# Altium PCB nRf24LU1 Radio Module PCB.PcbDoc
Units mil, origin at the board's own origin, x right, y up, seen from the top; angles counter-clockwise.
Board outline 2945 x 691.05 mil, 2 copper layers (Top Layer, Bottom Layer); 44 components, 44 nets, 168 pads, 119 vias.
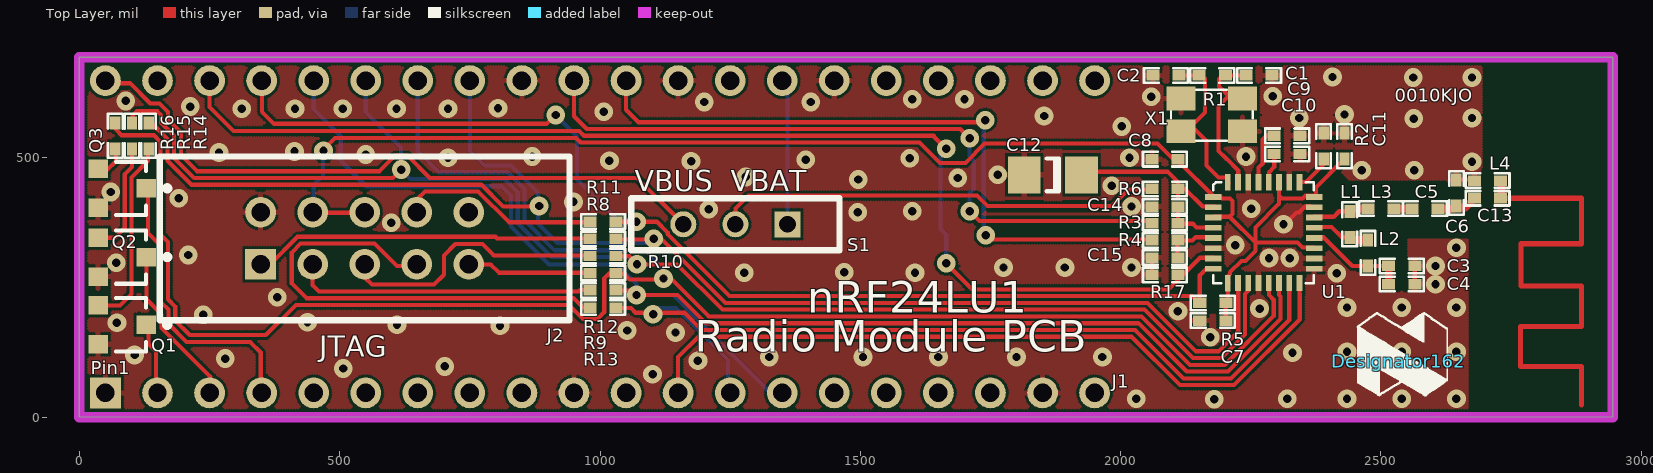
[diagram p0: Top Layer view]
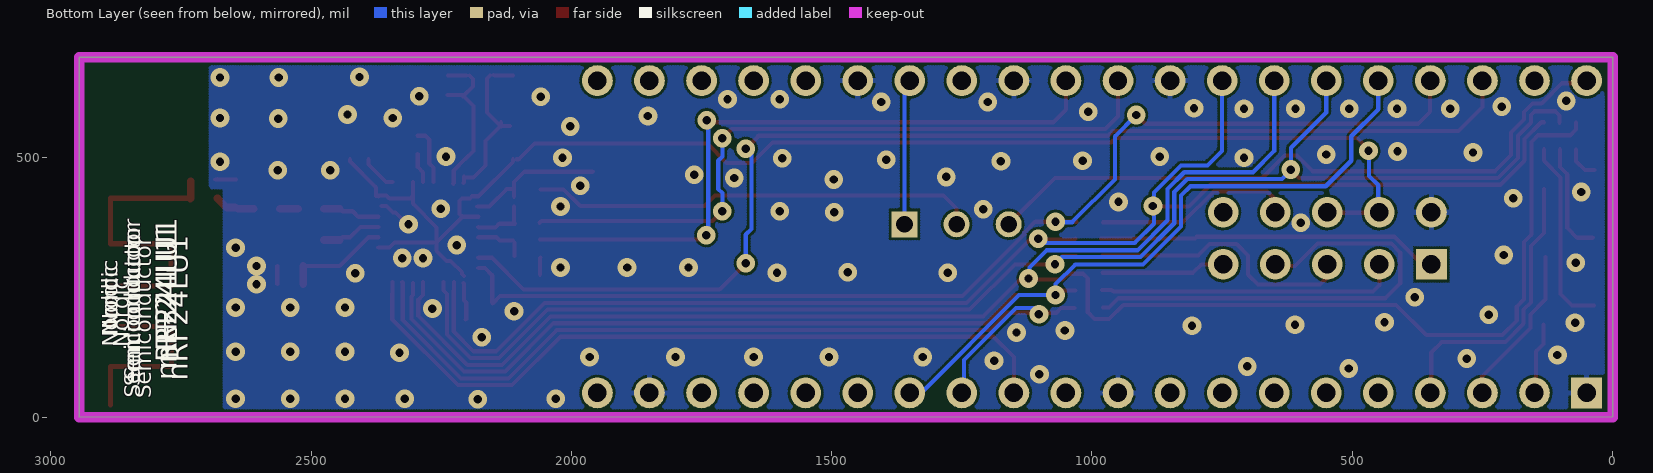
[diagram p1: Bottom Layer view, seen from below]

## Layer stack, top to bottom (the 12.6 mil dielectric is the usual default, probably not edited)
Top Layer: signal copper 1.4
Dielectric: dielectric 12.6, FR-4, Dk 4.8
Bottom Layer: signal copper 1.4

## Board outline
0,1 0,691.53 2945,691.53 2945,0.47

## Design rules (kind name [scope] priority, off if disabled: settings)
Clearance [All] p1: gap=5
ComponentClearance [All] p1 off: gap=10 collisioncheckmode=3 verticalgap=10
PolygonConnect PolygonConnect_1 [IsVia and InNet(GND)] p1: connectstyle=Direct reliefconductorwidth=10 reliefentries=4 polygonreliefangle="90 Angle"
PolygonConnect [All] p2: connectstyle=Relief reliefconductorwidth=10 reliefentries=4 polygonreliefangle="90 Angle"
RoomDefinition "nRF24LU1 Radio Module PCB" [InComponentClass('nRF24LU1 Radio Module PCB')] p1 off: confinementstyle=ConfineIn formatcopy=TRUE lockcomponents=FALSE outline 3275,55 3406,55 3406,259 3275,259
RoutingVias [All] p1: holewidth=10 width=20 viastyle="Through Hole" minholewidth=6 minwidth=10 maxholewidth=28 maxwidth=50
SolderMaskExpansion [All] p1: expansion=4
TestPointUsage [All] p1: valid=0 allowmultiple=FALSE
Testpoint [All] p1: side=15 testpointundercomponent=TRUE minsize=40 maxsize=100 preferedsize=60 minholesize=0 maxholesize=40 preferedholesize=32 testpointgrid=1 style=1023 order=0-112345678
Width [All] p1: maxlimit=50 minlimit=6 preferedwidth=10 toplayer_prefwidth=8 bottomlayer_prefwidth=8 minimp=50.000000 maximp=50.000000 favimp=50.000000
18 further rules are at their usual default settings.

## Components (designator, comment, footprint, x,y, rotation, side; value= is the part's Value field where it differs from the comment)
C1 "NPO, +/-2% 50V" 0402s 2266,657 r0 top
C2 "NPO, +/-2% 50V" 0402s 2087,657 r0 top
C3 "X7R, +/-10% 50V" 0402s 2540,291 r180 top
C4 "NP0 +/-0.25pF, 50V" 0402s 2540,256 r180 top
C5 "NP0 +/-0.1pF, 50V" 0402s 2585,401 r180 top
C6 "NP0 +/-0.1pF, 50V" 0402s 2645,431 r90 top
C7 "X7R, +/-10% 50V" 0402s 2177,186 r180 top
C8 "X7R, +/-10% 50V" 0402s 2085,496 r180 top
C9 "X7R, +/-10% 50V" 0402s 2320,541 r0 top
C10 "X7R, +/-10% 50V" 0402s 2320,506 r0 top
C11 "X7R, +/-10% 50V" 0402s 2430,521 r90 top
C12 "Tantal  10V" C1206 1870,466 r180 top
C13 "NP0 +/-0.25pF, 50V" 0402s 2705,421 r180 top
C14 "NP0, +/-10% 50V" 0402s 2085,405 r180 top
C15 "" 0402s 2085,307 r180 top
Designator162 "Comment" NordicSemi1 2534,108 r180 top
J1 "Elfa 48-155-10" DIP40 50,47 r90 top
J2 "Header 2x5 pin" IDC2X5 548,344 r0 top
L1 "Chip inductor +/-5%  Murata LQP15" 0402s 2440,371 r270 top
L2 "Chip Inductor +/-5%  Murata LQP15" 0402s 2475,316 r90 top
L3 "Chip inductor +/-5%  Murata LQP15" 0402s 2500,401 r0 top
L4 "Chip inductor +/-5% Murata LQP15" 0402s 2705,455 r0 top
Q1 "BC847C" SOT23 82,178 r270 top
Q2 "BC847C" SOT23 82,308 r270 top
Q3 "BC847C" SOT23 82,440 r270 top
R1 "5%" 0402s 2176,657 r180 top
R2 "1%" 0402s 2390,521 r270 top
R3 "5%" 0402s 2085,373 r180 top
R4 "5%" 0402s 2085,340 r180 top
R5 "5%" 0402s 2177,220 r0 top
R6 "5%" 0402s 2085,439 r180 top
R8 "" 0402s 1006,343 r180 top
R9 "" 0402s 1006,244 r180 top
R10 "" 0402s 1006,310 r180 top
R11 "" 0402s 1006,376 r180 top
R12 "" 0402s 1006,277 r180 top
R13 "" 0402s 1006,211 r180 top
R14 "5%" 0402s 133,541 r270 top
R15 "5%" 0402s 101,541 r270 top
R16 "5%" 0402s 69,541 r270 top
R17 "5%" 0402s 2085,274 r0 top
S1 "ELFA 35-365-21" "SW mini2" 1360,371 r180 top
U1 "nRF24LU1" QFN32L/5x5 2178,258 r0 top
X1 "TSX4025 16MHz, CL=9pF" BT-XTAL 2175,581 r180 top

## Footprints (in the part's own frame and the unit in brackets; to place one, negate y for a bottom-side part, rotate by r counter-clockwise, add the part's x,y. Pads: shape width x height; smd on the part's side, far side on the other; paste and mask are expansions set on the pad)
0402s [mil]
  rect 25x20 smd: 1(-25,0) 2(25,0)
  silkscreen extent -42,-14 42,14
BT-XTAL [mm]
  rect 1.4x1.15 smd: 1(-1.498,-0.801) 2(1.498,-0.801) 3(1.498,0.801) 4(-1.498,0.801)
  silkscreen extent -2,-1.23 1.98,1.26
C1206 [mm] "Chip Capacitor; Body 3.2 x 1.6 mm (LxW typ)"
  rect 1.6x1.8 smd: 1(-1.4,0) 2(1.4,0)
  silkscreen extent -0.3,-0.8 0.3,0.8
DIP40 [mm]
  rect 1.5x1.5 hole 0.9: 1(0,0)
  round 1.5 hole 0.9: 2(0,-2.54) 3(0,-5.08) 4(0,-7.62) 5(0,-10.16) 6(0,-12.7) 7(0,-15.24) 8(0,-17.78) 9(0,-20.32) 10(0,-22.86) 11(0,-25.4) 12(0,-27.94) 13(0,-30.48) 14(0,-33.02) 15(0,-35.56) 16(0,-38.1) 17(0,-40.64) 18(0,-43.18) 19(0,-45.72) 20(0,-48.26) 21(15.24,-48.26) 22(15.24,-45.72) 23(15.24,-43.18) 24(15.24,-40.64) 25(15.24,-38.1) 26(15.24,-35.56) 27(15.24,-33.02) 28(15.24,-30.48) 29(15.24,-27.94) 30(15.24,-25.4) 31(15.24,-22.86) 32(15.24,-20.32) 33(15.24,-17.78) 34(15.24,-15.24) 35(15.24,-12.7) 36(15.24,-10.16) 37(15.24,-7.62) 38(15.24,-5.08) 39(15.24,-2.54) 40(15.24,0)
IDC2X5 [mm]
  rect 1.5x1.5 hole 0.9: 1(-5.08,-1.27)
  round 1.5 hole 0.9: 2(-5.08,1.27) 3(-2.54,-1.27) 4(-2.54,1.27) 5(0,-1.27) 6(0,1.27) 7(2.54,-1.27) 8(2.54,1.27) 9(5.08,-1.27) 10(5.08,1.27)
  silkscreen extent -10,-4 10,4
NordicSemi1 [mil]
  silkscreen extent -94,-94 80,66
QFN32L/5x5 [mm]
  rect 0.8x0.28 smd: 1(-0.001,4.205) 2(-0.001,3.705) 3(-0.001,3.205) 4(-0.001,2.705) 5(-0.001,2.205) 6(-0.001,1.705) 7(-0.001,1.205) 8(-0.001,0.705) 17(4.917,0.705) 18(4.917,1.205) 19(4.917,1.705) 20(4.917,2.205) 21(4.917,2.705) 22(4.917,3.205) 23(4.917,3.705) 24(4.917,4.205)
  rect 0.28x0.8 smd: 9(0.71,0) 10(1.21,0.004) 11(1.71,0.004) 12(2.21,0.004) 13(2.71,0.004) 14(3.21,0.004) 15(3.71,0.004) 16(4.21,0.004) 25(4.21,4.921) 26(3.71,4.921) 27(3.21,4.921) 28(2.71,4.921) 29(2.21,4.921) 30(1.71,4.921) 31(1.21,4.921) 32(0.71,4.921)
  silkscreen extent 0,-0.01 4.9,4.92
SOT23 [mm] "SOT-23; 3 Leads; Body 3.1 x 2.5 mm, inc. leads (LxW max), Alternate Lead Configuration"
  rect 0.9x0.95 smd: 1(0,1.175) 2(0.95,-1.175) 3(-0.95,-1.175)
  silkscreen extent -1.3,-0.3 1.3,2.33
"SW mini2" [mil]
  rect 50x50 hole 32: 1(0,0)
  round 50 hole 32: 2(100,0) 3(200,0)
  silkscreen extent -100,-50 300,50

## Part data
C1 C2 C3 C4 C5 C6 C7 C8 C9 C10 C11 C13 C14 C15: library part CAP
C12: library part "Cap Pol3", "Polarized Capacitor (Surface Mount)"
J1: library part 40PIN
J2: library part "Header 6", "Header, 6-Pin"
L1 L2 L3 L4: library part INDUCTOR1
Q1 Q2 Q3: library part NPN, "NPN Bipolar Transistor"
R1 R2 R3 R4 R5 R6 R8 R9 R10 R11 R12 R13 R14 R15 R16 R17: library part RES2
S1: library part SW-SPDT, "SPDT Subminiature Toggle Switch, Right Angle Mounting, Vertical Actuation"
U1: library part nRF24LU01, "nRF24LU01"
X1: library part BT-XTAL

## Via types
v1: diameter 36, hole 16, Top Layer to Bottom Layer, tented both sides, 118 vias
v2: diameter 35.98, hole 15.98, Top Layer to Bottom Layer, tented both sides, 1 vias

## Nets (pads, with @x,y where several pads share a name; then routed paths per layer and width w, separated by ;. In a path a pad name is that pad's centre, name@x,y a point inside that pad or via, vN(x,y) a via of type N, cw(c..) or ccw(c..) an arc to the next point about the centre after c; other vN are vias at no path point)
CSN/TDO: J1.14 J1.36 R9.1 U1.14 | length 2706.7
  Top Layer w8: R9.1@1032,244 1061,244 v1(1070,235) 1149,235 1203,181 2034,181 2127,88 2206,88 2307,189 2307,232 2304,235 ; 2304.53,235.53 U1.14@2304.53,258.15
  Bottom Layer w7.99: 829,367 829,426
  Bottom Layer w8: J1.36@450,646 450,592 502,540 502,493 551,444 811,444 829,426 ; 829,367 902,294 1032,294 1070,256 v1(1070,235) 1140,235 1329,46 1348,46 J1.14@1350,48
D+: J1.31 R3.2 | length 1351.8
  Top Layer w8: J1.31@950,646 950,578.5 974.5,554 1692,554 v1(1710,536) ; v1(1710,396) 1729,377 2058,377 R3.2@2061,374
  Bottom Layer w8: v1(1710,396) 1710,431 1718,439 1718,493 1710,501 v1(1710,536)
D-: J1.30 R4.2 | length 1304.2
  Top Layer w8: J1.30@1050,646 1050,591 1074,567 1736,567 v1(1740,571) ; v1@1739,354 1751,342 R4.2@2060,342
  Bottom Layer w8: v1@1738,572 1737,571 1737,355 v1@1740,352
  other v1: 1741,350
GND: C1.2 C2.1 C3.1 C4.1 C6.2 C7.2 C8.2 C9.2 C10.2 C11.2 C12.2 C14.2 C15.2 J1.1 J1.10 J1.19 J1.26 J1.29 J1.32 J2.2 L4.1 Q1.2 Q2.2 Q3.2 R2.1 R17.1 U1.6 U1.12 U1.17 U1.18 U1.23 U1.26 U1.30 X1.2 X1.4 | length 160.2
  Top Layer w8: C15.2@2059,307 2060,306 R17.1 ; v1@2325,381 2337.53,393.53 2342.89,393.53 2355.36,406 U1.23@2365,406 ; C4.1 C3.1 ; C6.2@2644,457 L4.1@2684,457 ; L4.1@2680,458 L4.1@2681,457
  other v1: 2180,35 2030,36 2320,36 2435,36 2540,36 2645,36 1101,83 507,94 702,98 1188,109 280,113 1325,116 1505,116 1650,116 1800,116 1965,116 106,120 2330,124 2435,126 2540,126 2645,126 2172,154 1145,163 1052,167 808,176 610,178 72,182 438,183 238,197 2110,204 2267,209 2435,211 2540,211 2645,211 380,231 2605,256 2415,277 1277,278 1605,278 1469,279 1775,288 1893,288 2021,288 2605,291 2285,306 2325,306 209,312 2645,326 2220,331 2313,371 599,374 1495,394 1600,396 1209,400 2251,401 2021,405 949,414 191,421 60,433 1983,445 1496,457 1687,460 1280,462 1764,466 2463,475 2564,475 2675,491 1175,492 1018,493 1395,495 1595,498 708,499 2017,499 870,501 2241,501 550,505 268,509 413,511 2002,559 2563,574 2343,575 2675,575 1853,579 2430,582 1007,587 312,593 414,593 506,593 609,593 708,593 804,594 213,597 1200,606 1405,606 89,608 1600,611 1700,611 2059,616 2292,617 2562,653 2675,653 2407,654
  other v2: 71,297
LED1: J1.2 Q1.1 | length 135.8
  Top Layer w8: Q1.1@133,178 133,141 147,127 J1.2@147,48
LED2: J1.3 Q2.1 | length 310.9
  Top Layer w8: Q2.1@129,308 129,227 158,198 158,172 252,78 J1.3@252,48
LED3: J1.4 Q3.1 | length 552.6
  Top Layer w8: Q3.1@132,439 132,354 157,329 157,221 171,207 171,180 206,145 328,145 348.26,124.74 348.26,49.26 J1.4@347,48
LED4: J1.5
MISO/TDI: J1.34 R12.1 R16.1 U1.13 | length 3618.5
  Top Layer w8: R16.1@70,566 70,553 81,542 143,542 156,529 156,351 170,337 170,227 184,213 184,186 212,158 358,158 416,216 940,216 967,189 995,189 1008,202 1008,267 1017,276 1046,276 1057,265 1138,265 1209,194 2040,194 2133,101 2200,101 2294,195 2294,226 2284.84,235.16 U1.13@2284.84,259.89
  Bottom Layer w8: J1.34@650,646 650,512 691,471 822.75,471 855,438.75 855,378.75 912.75,321 1087,321 1120,288 v1@1120,276
  other v1: 1122,267
MOSI/TMS: J1.35 R10.1 R15.1 U1.11 | length 2805.3
  Top Layer w7.99: R15.1@102,566 102,580 110,588 150,588
  Top Layer w8: 150,588 157,581 157,566 182,541 182,498.44 220.44,460 602,460 v1@618.5,476.5 ; R10.1 1056,310 1072,294 1148,294 1235,207 2046,207 2139,114 2194,114 2239,159 2239,237.06 2245.47,243.53 U1.11@2245.47,259.89
  Bottom Layer w8: J1.35@550,646 550,586 618,518 v1@618,477 ; v1@617,477 617,476 635,458 817,458 842,433 842,373 907,308 1058,308 v1@1074,292
  other v1: 1071,294 618,476
NetC1_1: C1.1 R1.1 U1.31 X1.1 | length 309.2
  Top Layer w8: R1.1@2196,657 2189,650 2189,636 X1.1@2208,617 ; R1.1 C1.1@2237,657 ; 2202,498 2188,512 2188,598 2209,619 X1.1@2238,619 ; 2203,497 2226,474 2226,450 U1.31@2227,449
NetC2_2: C2.2 R1.2 U1.32 X1.3 | length 335.8
  Top Layer w8: C2.2 2148,657 R1.2@2149,658 ; X1.3@2118,560 2136,560 2165,531 2165,484 2188,461 2206,461 2206,451 U1.32@2207,450 ; X1.3@2135,567 2135,559 2162,586 2162,651 R1.2@2156,657 ; U1.32@2206.1,452.11 U1.32@2206.1,462.9
NetC3_2: C3.2 C4.2 L2.1 U1.20 | length 201.7
  Top Layer w8: U1.20@2371.11,346.16 2389.84,346.16 2445,291 C3.2
  Top Layer w15: C4.2 C3.2
NetC5_1: C5.1 C6.1 C13.2 | length 78.5
  Top Layer w8: C6.1@2640,401 C6.1
  Top Layer w15: C5.1 C6.1@2640,401 ; C6.1@2646,403 2662,403 C13.2
NetC5_2: C5.2 L3.2 | length 35
  Top Layer w15: L3.2 C5.2
NetC9_1: C9.1 U1.29 | length 110
  Top Layer w8: U1.29@2265.16,452.11 2265.16,480.16 2273,488 2273,534 2280,541 C9.1
NetC10_1: C10.1 U1.28 | length 58.1
  Top Layer w8: U1.28@2284.84,452.11 2284.84,470.84 2295,481 C10.1
NetC12_1: C12.1 R6.1 U1.2 | length 271.2
  Top Layer w8: 1959,472 2090,472 2110,452 2110,424 ; R6.1@2111,439 2124,439 2157.8,405.2 2177.96,405.2 U1.2@2180.89,405.21
NetC13_1: C13.1 L4.2 | length 1053.7
  Top Layer w10: C13.1 2885,421 2885,333.68 2769.11,333.68 2769.11,252.68 2885,252.68 2885,174.68 2768.11,174.68 2768.11,97.68 2885,97.68 2885,23.68 ; L4.2 L4.2@2730.69,454.32 ; C13.1@2732,418 C13.1@2733,419 ; L4.2@2732,451 L4.2@2733,452
  Top Layer w15: C13.1@2731,421 L4.2@2731,453
NetC14_1: C14.1 R3.1 U1.4 | length 106
  Top Layer w8: R3.1@2108,372 2110,374 C14.1 ; R3.1@2110,372 2138.68,372 2145.68,365 2178.05,365 U1.4@2178.89,365.84
NetC15_1: C15.1 R4.1 U1.5 | length 95.4
  Top Layer w8: C15.1@2109,310 R4.1@2109,336 ; R4.1@2112,340 2138,340 2144.16,346.16 U1.5@2178.89,346.16
NetJ2_1: J2.1 R8.2 | length 657.6
  Top Layer w8: J2.1@349,293 365,293 419,347 799,347 802,344 R8.2@983,344
NetJ2_3: J2.3 R9.2 | length 576.2
  Top Layer w8: J2.3@448,291 448,254 460,242 959,242 962,245 R9.2@981,245
NetJ2_5: J2.5 R10.2 | length 520.1
  Top Layer w8: J2.5@550,289 550,267 562,255 681,255 700,274 700,311 722,333 774,333 796,311 R10.2@980,311
NetJ2_7: J2.7 R13.2 | length 916.9
  Top Layer w8: J2.7@650,291 610,291 567,334 425,334 408,317 408,257 436,229 949,229 967,211 R13.2@979,211
NetJ2_8: J2.8 R11.2 | length 391.3
  Top Layer w8: J2.8@653,390 649,394 649,419 664,434 766,434 825,375 R11.2@979,375
NetJ2_9: J2.9 R12.2 | length 236
  Top Layer w8: J2.9@751,293 752,294 790,294 806,278 R12.2@980,278
NetL1_1: L1.1 L3.1 U1.22 | length 110.3
  Top Layer w8: U1.22@2371.11,385.53 2409.53,385.53 2420,396 L1.1 L1.1@2445,401
  Top Layer w15: L1.1@2445,401 L3.1
NetL1_2: L1.2 L2.2 U1.21 | length 114.2
  Top Layer w8: U1.21@2371.11,365.84 2405.16,365.84 2425,346 L1.2 L1.2@2445,341
  Top Layer w15: L1.2@2445,341 L2.2
NetQ1_2: Q1.3 R14.2 | length 364.4
  Top Layer w8: Q1.3@36,215 78,215 100,237 100,461 132,493 R14.2@132,515
NetQ2_2: Q2.3 R15.2 | length 213.7
  Top Layer w8: Q2.3@38,345 68,345 87,364 87,466.94 101,480.94 R15.2@101,515
NetQ3_2: Q3.3 R16.2 | length 64
  Top Layer w8: Q3.3@35,475 53,475 70,492 R16.2@70,514
NetR2_2: R2.2 U1.25 | length 70.1
  Top Layer w8: U1.25@2343.9,452.11 2356.11,452.11 2390,486 R2.2
NetR6_2: R6.2 S1.2 | length 860.9
  Top Layer w8: S1.2 1260,401 1285,426 1724,426 1744,406 1983,406 2015,438 R6.2@2059,438
P0.4: J1.13 R13.1 U1.15 | length 1714.1
  Top Layer w8: R13.1@1034,210 1059.31,210 1068.31,201 1162,201 1195,168 2028,168 2121,75 2211.94,75 2324,187.06 2324,259 U1.15@2325,260
  Bottom Layer w8: v1@1102,210 1146,210 1246,110 J1.13@1246,47
  other v1: 1102,198
P0.5: J1.12 U1.16 | length 1442.8
  Top Layer w8: J1.12@1150,46 1150,116 1189,155 2021,155 2114,62 2217.94,62 2344,188.06 2344,236.8 2343.9,236.9 U1.16@2343.9,259.89
PROG: J1.38 R17.2 U1.7 | length 2288
  Top Layer w8: J1.38@250,646 250,596 296,550 960,550 969,541 1641,541 ; 1640,541 v1(1665,516) ; v1(1665,296) 1715,246 2092,246 2152.79,306.79 U1.7@2178.89,306.79
  Bottom Layer w8: v1(1665,296) 1665,351 1654,362 1654,505 v1(1665,516)
RESET: J1.37 R5.1 R11.1 U1.8 | length 2203.6
  Top Layer w7.99: J1.37@351,645 351,587 374,564 897,564 v1@914.5,581.5 ; R5.1@2152,221 2152,273 2166.1,287.1 U1.8@2178.89,287.1
  Top Layer w8: R11.1@1030,376 1109,376 1130,355 1130,351.94 1248.94,233 2137,233 R5.1@2151,219
  Bottom Layer w7.99: v1(915,581) 956,540 956,457 1038,375 1069,375 1069,373 v1@1071,375
  other v1: 1070,376
SCK/TCK: J1.33 R8.1 R14.1 U1.10 | length 2838.9
  Top Layer w7.99: 814,405 v1@884,405
  Top Layer w8: R14.1@132,567 137,567 169,535 169,493 215,447 772,447 814,405 ; R8.1@1032,344 1034,342 1119,342 1241,220 2051.61,220 2144.61,127 2188,127 2226,165 2226,243 2225.79,243.21 U1.10@2225.79,259.89
  Bottom Layer w8: J1.33@750,646 750,512 778,484 829,484 881,432 881,372 918,335 1094,335 v1@1104,345
  other v1: 1103,343 883,406
VBAT: J1.40 S1.3 | length 1278.9
  Top Layer w8: J1.40@52,642 97,642 136,603 153.75,603 170,586.75 170,572 195,547 195,504 226,473 576.19,473 606.19,503 630,503 673,460 1071,460 S1.3
VBUS: J1.27 S1.1 | length 286.2
  Top Layer w8: S1.1 S1.1@1365,366
  Bottom Layer w8: J1.27@1350,646 1360,636 S1.1
VDD: J1.28
VDD_NRF: C7.1 C8.1 C11.1 J2.4 J2.6 R5.2 U1.1 U1.3 U1.9 U1.19 U1.24 U1.27 | length 2779.9
  Top Layer w8: J2.4@447,393 J2.6@552,393 ; v1@469,513 469,515 491,537 954,537 963,528 1614,528 1653,489 1701.75,489 1738.75,526 2071,526 2101,496 C8.1@2105,496 ; C8.1@2112,496 2112,491 U1.1@2178,425 ; U1.1@2177.79,426 2178.89,424.9 2190.59,424.9 2194.76,420.72 2210.28,420.72 2215,416 2215,391 2209.53,385.53 ; U1.3@2178.89,385.53 2209.53,385.53 ; C7.1@2203,188 2202,189 2202,221 2206,225 2206,257 U1.9@2207,258 ; U1.9@2206.1,271.59 2210.28,275.76 2210.28,278.99 2231.98,300.69 2239.69,300.69 2259.06,320.06 2259.06,365.06 2304.53,410.53 U1.27@2304.53,452.11 ; 2304.53,426.47 2310.23,420.77 2349.77,420.77 2355,426 2370.01,426 U1.24@2371.11,424.9 ; U1.19@2371.11,326.47 2349.53,326.47 2340,336 2259.06,336 2209.53,385.53 ; U1.24@2375,425 2375,442 2425,492 C11.1@2425,496
  Bottom Layer w8: J2.4@450,391 450,446 468,464 v1@468,513
  other v1: 469,512
VDD_REG_RF: J1.39
pads on no net: J1.6 J1.7 J1.8 J1.9 J1.11 J1.15 J1.16 J1.17 J1.18 J1.20 J1.21 J1.22 J1.23 J1.24 J1.25 J2.10

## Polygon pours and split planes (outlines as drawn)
GND on Top Layer "Top Layer-GND" (hatched 90Degree grid 5 track 6, remove dead copper, pour order 1000): -70,731 2693,731 2693,-49 -64.94,-49
GND on Bottom Layer "Bottom Layer-GND" (hatched 90Degree grid 5 track 7.99, remove dead copper, pour order 1001): 2693,-84 2693,751 -80,751 -80,-79

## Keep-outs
Keep-Out Layer:
  lines w20: 0.01,0.47 2945,0.47 2945,691.53 0,691.53 0,1 0.01,0.47

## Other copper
Top Layer:
  pour cut-out: 993,391 1018,391 1018,197 993,197
  pour cut-out: 2231,591 2231,571 2207,571 2207,591
  pour cut-out: 2119,594 2119,568 2140,568 2140,594
  pour cut-out: 2389,433 2353,433 2353,440 2394,481 2418,481 2439,457 2438,457 2439,457 2438,457 2670,457 2670,341 2553,341 2553,241 2495,241 2495,271 2460,271 2415,321 2389.84,346.16 2390.07,431.07
  pour cut-out: 2401,513 2419,513 2419,481 2401,481
  pour cut-out: 2160,196.5 2194,196.5 2194,271.5 2160,271.5
  pour cut-out: 2747,441.5 2666,441.5 2666,8.5 2747,8.5
Bottom Layer:
  pour cut-out: 2747,441.5 2666,441.5 2666,8.5 2747,8.5

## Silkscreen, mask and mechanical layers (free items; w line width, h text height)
Top Overlay:
  text "0010KJO" at 2527,606 h25
  text "VBUS  VBAT" at 1067,434 h40
  text "nRF24LU1" at 1398,201 h60
  text "Radio Module PCB" at 1182,126 h60
  text "JTAG" at 461,117 h40
Bottom Overlay:
  text "Nordic" at 2871,169 h30 r270
  text "Nordic" at 2871,158 h30 r270
  text "Nordic" at 2871,136 h30 r270
  text "Nordic" at 2850,135 h30 r270
  text "nRF24LU1" at 2758,104 h40 r270
  text "nRF24LU1" at 2758,93 h40 r270
  text "nRF24LU1" at 2758,71 h40 r270
  text "Semiconductor" at 2828,71 h30 r270
  text "nRF24LU1" at 2737,70 h40 r270
  text "Semiconductor" at 2828,60 h30 r270
  text "Semiconductor" at 2828,38 h30 r270
  text "Semiconductor" at 2807,37 h30 r270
